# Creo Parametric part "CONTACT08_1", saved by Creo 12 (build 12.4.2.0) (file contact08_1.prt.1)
Units: Custom; MM, KILOGRAM, SECS

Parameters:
  PTC_WM_ITERATION = "0"
  PTC_WM_VERSION = "-.0"
  PTC_WM_LIFECYCLE_STATE = "In Work"
  PTC_WM_LIFECYCLE = "MO_CADDocument"
  PTC_WM_CREATED_BY = "Maximilian Roepper (Z0017RMS: MO)"
  PTC_WM_CREATED_ON = "18-Sep-26 11:36:42 AM"
  PTC_WM_MODIFIED_BY = "Maximilian Roepper (Z0017RMS: MO)"
  PTC_WM_MODIFIED_ON = "18-Sep-26 11:36:46 AM"
  PDMLINKNUMBER = "PDM000071455183"
  PTC_WM_NAME = "contact08_1.prt"
  PTC_WM_NUMBER = "PDM000071455183"

Other parameters: WEIGHT, WEIGHT_FACTOR, WEIGHT_ADD, _MASS_TEMP, _DIFF_TEMP, MC_ERRORS, SUPPLIER

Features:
  1. coordinate system
  2. datum plane "PRT_YZ"
  3. datum plane "PRT_XY"
  4. datum plane "PRT_XZ"
  5. coordinate system
  6. datum axis
  7. datum axis
  8. datum axis
  9. coordinate system
  10. imported feature

Other named items: PRT, SIEMENS_MO, DRW_VIEW_ORG, PRT_X, PRT_Y, PRT_Z, CS0, ROUGH_GROB

Layers: 00_STD_CSYS-KSYS, 01_STD_PLANES-EBENEN, 02_STD_AXES-ACHSEN, 03_STD_CSYS-KSYS, 24_IMPORT_FEAT-IMPORT_KE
